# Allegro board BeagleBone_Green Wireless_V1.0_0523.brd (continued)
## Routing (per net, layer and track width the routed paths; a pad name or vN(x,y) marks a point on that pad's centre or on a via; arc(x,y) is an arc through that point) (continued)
LEDDC: length 19.3
  TOP w0.121: v1(19.7,108.05) 19.41,108.05 19.32,108.14 Q2.3 ; v1(4.57,110.08) 4.7,109.96 D5.1
  LYR3 w0.133: v1(4.57,110.08) 5.71,110.08 5.87,110.24 7.65,110.24 9.45,112.04 15.09,112.04 19.08,108.05 v1(19.7,108.05)
MMC0_CD: length 83.8
  TOP w0.121: v1(42.32,88.73) U5.C15
  LYR3 w0.127: v1(37.06,83.78) 37.33,84.05 47.9,84.05
  LYR3 w0.133: 47.9,84.05 48.79,84.94 53.11,84.94 53.8,84.25 54.61,84.25 55.91,82.96 55.91,81.13 56.62,80.42 68.38,80.42 72.67,84.71 72.67,91.31 75.57,94.21 v1(76.58,94.21) 77.93,95.55 77.93,103.9 v1(75.62,106.2)
  BOTTOM w0.121: 36.8,84.41 36.8,85.29 37.49,85.98 40.93,85.98 41.92,86.97 41.92,88.33 v1(42.32,88.73) ; P10.10 73.19,108.82 73.58,108.43 73.58,108.24 v1(75.62,106.2) ; R157.1 v1(76.58,94.21) ; 35.92,83.86 P2.19
  BOTTOM w0.127: 35.92,83.86 36.57,83.86 36.65,83.78 v1(37.06,83.78) 37.06,84.16 36.8,84.41
MMC0_CLKO: length 84
  TOP w0.121: v1(33.6,85.34) 33.6,85.9 34.8,87.1 34.8,88.3 37.66,91.16 38.48,91.16 40.06,92.74 40.72,92.74 U5.G17
  LYR3 w0.133: v1(84.53,94.41) 84.3,94.64 83.27,94.64 81.25,92.62 81.25,91.12 80.95,90.82 80.95,86.26 77.04,82.35 72.55,82.35 69.48,79.27 56.82,79.27 54.43,76.88 50.32,76.88 50.32,76.89 49.1,76.89 48.23,77.75 48.23,78.81 47.21,79.83 46.48,79.83 45.22,81.1 45.22,81.47 43.78,82.91 40.67,82.91 39.6,81.84 36.78,81.84 36.09,81.15 35.57,81.15 33.22,83.5 33.22,84.96 v1(33.6,85.34)
  BOTTOM w0.121: P10.5 85.09,94.97 v1(84.53,94.41) 85.34,93.6 R152.2
MMC0_CMD: length 94.8
  TOP w0.121: U5.G18 40.04,92.34 38.61,90.91 37.75,90.91 35.1,88.26 35.1,86.77 34.01,85.67 34.01,85.04 v1(33.63,84.66)
  LYR3 w0.133: v1(33.63,84.66) 33.63,83.96 35.54,82.04 36.2,82.04 36.32,82.17 39.6,82.17 40.57,83.14 44.11,83.14 45.62,81.64 45.62,81.03 46.48,80.16 47.45,80.16 48.64,78.97 48.64,77.67 49.19,77.12 50.41,77.12 50.42,77.12 54.28,77.12 56.74,79.57 69.45,79.57 72.69,82.81 77,82.81 80.44,86.26 80.44,90.22 79.83,90.83 79.83,92.94 79.27,93.5 v1(79.27,94.08) 79.45,94.26 79.45,100 84.71,105.26 v1(84.71,107.57)
  BOTTOM w0.121: R151.2 79.27,93.34 v1(79.27,94.08) ; P10.3 84.39,109.21 84.71,108.89 v1(84.71,107.57)
MMC0_DAT0: length 72.9
  TOP w0.121: v1(41.52,91.94) U5.G16
  LYR3 w0.133: v1(41.1,81.89) 41.53,81.89 41.68,82.04 43.98,82.04 44.3,81.73 44.3,79.12 44.6,78.82 45.74,78.82 48.14,76.42 50.12,76.42 50.12,76.41 54.67,76.41 57,78.74 69.61,78.74 72.51,81.64 77.6,81.64 82.37,86.41 82.37,89.94 82.4,89.97 82.4,90.78 83.95,92.33 v1(83.95,94.23)
  LYR4 w0.133: v1(41.52,91.94) 41.32,91.94 39.22,89.84 39.22,86.72 39.6,86.33 39.6,83.31 41.02,81.89 v1(41.1,81.89)
  BOTTOM w0.121: P10.7 83.69,94.49 v1(83.95,94.23) 84.46,93.73 R153.2
MMC0_DAT1: length 70.9
  TOP w0.121: v1(42.32,91.94) U5.G15
  LYR3 w0.127: 49,76.65 48.24,76.65
  LYR3 w0.133: v1(41.1,82.5) 43.86,82.5 44.79,81.57 44.79,80.94 46.02,79.71 46.02,78.86 48.24,76.65 ; v1(83.24,94.03) 83.24,92.08 81.28,90.12 81.28,85.93 77.24,81.89 72.43,81.89 69.53,78.99 56.92,78.99 54.58,76.65 50.22,76.65 50.22,76.65 49,76.65
  LYR4 w0.121: 39.51,86.97 39.47,87 39.47,87.22 ; 39.85,86.62 39.85,83.75 v1(41.1,82.5) ; v1(42.32,91.94) 41.92,91.54 41.35,91.54 41.13,91.32
  LYR4 w0.133: 39.85,86.62 39.51,86.97 ; 41.13,91.32 39.47,89.66 39.47,87.22
  BOTTOM w0.121: R154.2 83.52,93.37 83.52,93.75 v1(83.24,94.03) 82.99,94.27 P10.8
MMC0_DAT2: length 86.5
  TOP w0.121: v1(34.42,84.68) 34.82,85.09 34.83,85.09 34.95,85.21 34.95,86.16 35.41,86.61 35.41,88.21 37.86,90.66 38.74,90.66 39.62,91.54 U5.F18
  LYR3 w0.133: v1(83.52,105.36) 83.52,104.78 78.7,99.96 78.7,95.95 77.47,94.72 v1(77.47,94.08) 77.01,93.62 75.49,93.62 72.92,91.06 72.92,84.58 68.52,80.18 56.52,80.18 55.63,81.07 55.63,82.72 54.4,83.95 53.64,83.95 53.05,84.54 48.83,84.54 47.42,83.13 45.49,83.13 45.02,83.61 37.71,83.61 37.49,83.39 37.22,83.39 37.2,83.37 36.14,83.37 34.82,84.68 v1(34.42,84.68)
  BOTTOM w0.121: P10.1 82.99,109.23 83.44,108.79 83.44,105.81 83.52,105.74 v1(83.52,105.36) ; R150.2 v1(77.47,94.08)
MMC0_DAT3: length 87.8
  TOP w0.121: v1(35.71,82.45) 35.44,82.72 35.34,82.72 34.92,83.13 34.92,84.83 35.2,85.11 35.2,86.05 35.71,86.56 35.71,88.14 37.99,90.41 38.86,90.41 39.58,91.13 40.71,91.13 U5.F17
  LYR3 w0.133: v1(35.71,82.45) 39.55,82.45 40.47,83.38 44.84,83.38 45.32,82.9 47.75,82.9 48.91,84.06 52.89,84.06 55.37,81.57 55.37,81 56.42,79.95 68.67,79.95 73.23,84.51 73.23,90.78 75.46,93.01 77.32,93.01 v1(78.36,94.06) 78.36,95.1 79.02,95.76 79.02,99.9 84.05,104.93 v1(84.05,107.65)
  BOTTOM w0.121: v1(84.05,107.65) 84.05,108.02 84,108.07 84,109.35 83.69,109.65 P10.2 ; R155.2 v1(78.36,94.06)
MMC1_CLK: length 36.8
  TOP w0.076: U13.M6 29.32,107.79 v1(29.49,107.62)
  TOP w0.121: v1(44.68,113.43) 44.68,113.21 45.34,112.55 45.34,106.83 46.25,105.92 46.25,105.12 47.7,103.67 47.7,102.7 48.07,102.34 48.07,101.45 47.92,101.3 47.92,100.74 U5.U9
  LYR4 w0.133: v1(44.68,113.43) 44.2,112.95 40.06,112.95 37.82,110.72 31.67,110.72 30.12,109.17 30.12,108.13 29.62,107.62 v1(29.49,107.62)
  BOTTOM w0.121: P8.21 45.03,113.84 45.03,113.79 v1(44.68,113.43) 44.58,113.33 R110.2
MMC1_CMD: length 37.8
  TOP w0.076: v1(29.49,108.18) 29.38,108.29 U13.M5
  TOP w0.121: P8.20 44.98,116.79 44.98,114.68 44.53,114.22 44.45,114.22 v1(43.76,113.54) 44.93,112.37 44.93,106.88 46,105.82 46,105.02 47.42,103.6 47.42,102.61 47.82,102.21 47.82,101.64 47.52,101.34 U5.V9
  LYR4 w0.133: v1(29.49,108.18) 29.87,108.56 29.87,109.25 31.62,111 37.62,111 40.16,113.54 v1(43.76,113.54)
  BOTTOM w0.121: v1(43.76,113.54) 43.56,113.33 R109.2
MMC1_DAT0: length 48
  TOP w0.121: U13.A3 34.75,109.29 35.03,109.56 35.03,112.47 35.73,113.18 35.73,113.67 35.37,114.03 35.37,116.09 v1(35.64,116.36) ; P8.25 50.52,115.29 49.56,114.33 48.23,114.33 47.61,113.71 47.61,111.93 47.64,111.9 47.64,111.45 46.96,110.77 46.96,107.44 47.24,107.16 47.24,105.53 48.7,104.07 48.7,104.05 49.36,103.39 49.36,101.71 49.51,101.56 49.51,100.73 U5.U7
  LYR3 w0.133: P8.25 50.29,116.56 38.25,116.56 37.67,115.98 37.03,115.98 36.65,116.36 v1(35.64,116.36)
  BOTTOM w0.121: R101.2 49.02,112.88 50.67,114.53 50.8,114.53 P8.25
MMC1_DAT1: length 37.7
  TOP w0.121: v1(47.21,112.75) 46.72,112.26 46.72,107.34 46.98,107.07 46.98,107.02 46.99,107.01 46.99,105.43 48.45,103.97 48.45,103.95 49.12,103.28 U5.V7 ; U13.A4 35.01,108.79 35.56,109.33 35.56,112.25 36.44,113.13 37.62,113.13 v1(38.02,113.54)
  LYR4 w0.133: v1(47.21,112.75) 45.96,114 40.23,114 39.57,113.33 38.23,113.33 v1(38.02,113.54)
  BOTTOM w0.121: v1(47.21,112.75) R102.2 48.13,112.75 48.77,113.39 48.89,113.39 50.42,114.91 50.42,116.43 P8.24
MMC1_DAT2: length 43.8
  TOP w0.121: v1(38.18,112.2) 37.71,112.67 37.15,112.67 37.03,112.55 37.03,112.01 36.07,111.05 36.07,109.02 35.46,108.41 35.34,108.29 U13.A5 ; v1(48.72,99.14) U5.R8
  LYR3 w0.121: 48.32,100.18 48.32,99.54 v1(48.72,99.14)
  LYR3 w0.133: v1(38.18,112.2) 38.47,112.2 38.57,112.31 42.98,112.31 44.11,111.18 44.81,111.18 47.18,108.8 47.18,107.02 47.62,106.58 47.62,100.87 48.32,100.18
  LYR4 w0.133: v1(27.43,113.39) 28.8,112.01 34.67,112.01 35.59,112.93 37.45,112.93 v1(38.18,112.2)
  BOTTOM w0.121: R103.2 v1(27.43,113.39) 27.43,114.02 P8.5
MMC1_DAT3: length 39.9
  TOP w0.076: 34.29,110.85 34.29,110.54 34.24,110.49 34.24,110.05 33.99,109.8 U13.B2
  TOP w0.121: 34.29,110.85 34.29,112.4 34.32,112.42 v1(34.32,112.47) ; v1(48.72,99.94) U5.T8
  LYR3 w0.133: v1(34.32,112.47) 34.7,112.47 34.86,112.64 42.98,112.64 44.19,111.43 44.91,111.43 47.52,108.82 47.52,107.37 47.52,107.36 47.52,107.24 47.89,106.88 47.89,101.19 48.72,100.36 v1(48.72,99.94)
  LYR4 w0.133: v1(28.7,113.39) 29.59,112.5 34.24,112.5 34.26,112.47 v1(34.32,112.47)
  BOTTOM w0.121: P8.6 27.43,116.56 27.43,114.66 v1(28.7,113.39) R104.2
MMC1_DAT4: length 41.9
  TOP w0.076: 34.77,109.66 34.65,109.54 34.59,109.54 34.26,109.54 34,109.29 U13.B3
  TOP w0.121: U5.U8 48.71,100.73 48.71,102.44 48.21,102.95 48.21,103.87 46.74,105.33 46.74,106.18 46.62,106.31 46.18,106.74 46.18,107.07 46.47,107.36 46.47,112.36 46.81,112.7 46.81,112.92 46.86,112.97 46.86,113.39 48.1,114.62 48.35,114.62 P8.23 ; v1(34.67,113.39) 34.67,113.13 34.77,113.03 34.77,109.66
  LYR3 w0.133: P8.23 48.06,116.26 38.43,116.26 37.49,115.32 37.49,114.99 36.83,114.33 35.51,114.33 34.67,113.49 v1(34.67,113.39)
  BOTTOM w0.121: P8.23 46.61,112.88 R105.2
MMC1_DAT5: length 44.9
  TOP w0.076: 34.79,109.04 34.24,109.04 U13.B4
  TOP w0.121: 34.79,109.04 34.92,109.04 35.28,109.4 35.28,112.32 36.37,113.41 37.09,113.41 37.38,113.7 37.38,116.39 v1(37.38,116.4) ; P8.22 46.48,117.5 47.51,116.47 47.51,114.85 46.76,114.1 46.76,113.63 46.62,113.49 46.62,113.08 46.56,113.02 46.56,112.8 46.22,112.47 46.22,107.46 45.94,107.18 45.94,106.58 46.49,106.02 46.49,105.23 47.96,103.76 47.96,102.85 48.32,102.49 U5.V8
  LYR3 w0.133: P8.22 46.48,117.63 45.69,116.84 38.05,116.84 37.71,116.5 37.48,116.5 v1(37.38,116.4)
  BOTTOM w0.121: R106.2 47.75,114.91 47.75,116.56 P8.22
MMC1_DAT6: length 42.6
  TOP w0.076: U13.B5 34,108.29 34.25,108.53 34.87,108.53
  TOP w0.121: v1(47.92,99.14) U5.R9 ; v1(36.47,112.2) 35.81,111.54 35.81,109.19 35.79,109.17 35.79,109.14 35.18,108.53 35.05,108.53 34.87,108.53
  LYR3 w0.133: v1(47.92,99.14) 45.03,102.02 45.03,102.06 45,102.09 45,102.16 44.99,102.17 44.99,105.79 44.98,105.79 44.98,105.87 44.42,106.43 44.42,107.75 43.31,108.86 43.31,110.13 41.91,111.53 37.15,111.53 v1(36.47,112.2)
  LYR4 w0.133: v1(36.47,112.2) 35.8,112.2 35.03,111.43 26.85,111.43 v1(24.89,113.39)
  BOTTOM w0.121: P8.3 24.89,114.02 v1(24.89,113.39) R107.2
MMC1_DAT7: length 45.6
  TOP w0.076: 34.82,108.03 34.8,108.04 34.39,108.04 34.39,108.04 34.25,108.04 U13.B6
  TOP w0.121: v1(47.92,99.94) U5.T9 ; v1(37.52,112.2) 37.29,111.97 37.29,111.81 36.32,110.84 36.32,108.91 36.22,108.82 36.22,108.76 35.48,108.03 34.82,108.03
  LYR3 w0.133: v1(47.92,99.94) 47.66,99.94 45.59,102.01 45.59,103.45 45.64,103.51 45.64,103.58 46.1,104.04 46.1,105.13 44.7,106.53 44.7,109.07 41.99,111.79 37.94,111.79 v1(37.52,112.2)
  LYR4 w0.133: v1(26.16,113.39) 27.84,111.71 34.82,111.71 35.79,112.67 36.93,112.67 37.19,112.41 37.31,112.41 v1(37.52,112.2)
  BOTTOM w0.121: R108.2 v1(26.16,113.39) 24.89,114.66 24.89,116.56 P8.4
OSC0_IN: length 19.5
  TOP w0.121: U5.V10 46.72,101.66 46.69,101.69 46.69,102.52 46.81,102.64 46.81,103.26 v1(46.65,103.42)
  LYR3 w0.133: v1(45.82,108.51) 45.82,106.55 47.14,105.23 47.14,103.91 v1(46.65,103.42)
  BOTTOM w0.121: U17.5 44.19,108.17 44.53,108.51 v1(45.82,108.51) ; R234.1 38.18,103.66 38.64,103.66
  BOTTOM w0.133: v1(46.65,103.42) 46.26,103.42 46.03,103.66 45.82,103.66 45.76,103.71 44.21,103.71 44.12,103.81 42.57,103.81 42.39,103.63 40.99,103.63 40.81,103.45 40.47,103.45 40.27,103.66 38.64,103.66
OSC0_OUT: length 22.3
  TOP w0.121: U5.U11 46.31,100.73 v1(46.31,102.97)
  LYR3 w0.133: 46.23,103.13 46.23,103.09 46.31,103.01 v1(46.31,102.97) 46.31,102.97
  BOTTOM w0.121: v1(46.31,102.97) 45.88,103.4 45.71,103.4 45.66,103.46 44.11,103.46 44.01,103.56 42.67,103.56 42.5,103.38 41.12,103.38 40.83,103.09 36.76,103.09 36.09,103.76 36.09,110.72 36.5,111.12 R235.1
OSC1_IN: length 8.2
  TOP w0.121: U5.A6 51.05,86.4 51.05,85.7 50.93,85.57 50.93,84.18 51.56,83.54 v1(51.56,82.91) 51.56,82.08 51.33,81.84 Y1.1
  BOTTOM w0.121: C21.2 51.88,82.59 v1(51.56,82.91)
OSC1_OUT: length 8.6
  TOP w0.121: U5.A4 51.52,87.01 51.75,86.78 51.75,85.51 51.56,85.32 51.56,84.43 52.45,83.54 52.83,83.54 v1(53.47,82.91) 53.47,82.08 53.7,81.84 Y1.4
  BOTTOM w0.121: C22.2 53.15,82.59 v1(53.47,82.91)
OVCUR1#: length 1.8
  TOP w0.121: R224.1 29.59,94.21 28.7,95.1 U23.25
P_BYPASS: length 2.6
  TOP w0.203: v1(21.62,84.28) 21.65,84.24 22.22,84.24 22.46,84.01 U2.47
  BOTTOM w0.381: C4.2 21.59,84.25 v1(21.62,84.28)
P_INT_LDO: length 3.1
  TOP w0.121: U2.48 22.06,83.71 21.97,83.79 21.36,83.79 21.11,84.05 21.11,84.77 21.78,85.45 C3.2
P_L1: length 1
  TOP w0.203: U2.20 24.86,76.3
  vias: v1(23.75,75.03) v1(24.38,75.03)
P_L2: length 0.6
  TOP w0.203: 26.06,76.66 U2.23
  vias: v1(26.04,75.03) v1(26.67,75.03)
PGANG: length 20
  TOP w0.121: U23.23 28.66,94.1 29.18,93.57 v1(30.23,93.57) ; v1(18.9,91.74) 18.62,91.74 18.16,91.29 D6.1
  BOTTOM w0.121: v1(18.9,91.74) 18.9,91.93 19.02,92.05 R220.2 20.12,91.62 20.12,91.54 21.69,89.97 30.3,89.97 30.86,90.53 30.86,92.56 30.49,92.93 30.49,93.33 30.24,93.57 v1(30.23,93.57)
PMIC_INT: length 24.1
  TOP w0.121: U2.45 23.26,84.48 v1(22.99,84.75) 23.05,84.75 23.75,85.45 R1.2 ; v1(38.35,84.81) 38.35,85.52 38.99,86.16 38.99,87.01 U5.B18
  LYR3 w0.133: v1(38.35,84.81) 37.85,84.3 36.2,84.3 34.59,85.9 31.67,85.9 30.63,84.86 27.51,84.86 27.18,85.19 23.43,85.19 v1(22.99,84.75)
PMIC_PGOOD: length 30.1
  TOP w0.121: U2.26 27.75,78.57 27.95,78.36 27.95,78.26 v1(28.32,77.89) ; v1(32.08,75.77) 32.83,75.77 33.15,75.45 U16.2 ; v1(42.32,87.93) U5.B15
  LYR3 w0.133: v1(28.32,77.89) 30.44,75.77 31.35,75.77 31.35,75.77 31.69,75.77 31.69,75.77 v1(32.08,75.77) 34.37,75.77 36.47,77.88 38.33,77.88 39.7,79.25 42.93,79.25 43.51,79.83 v1(43.51,79.91)
  LYR4 w0.133: v1(43.51,79.91) 43.15,80.26 43.15,84.15 42.9,84.4 42.9,85.95 42.32,86.54 v1(42.32,87.93)
PMIC_POWR_EN: length 65.5
  TOP w0.121: U2.9 19.83,79.37 v1(19.71,79.25) ; v1(50.32,88.73) U5.C6
  LYR3 w0.133: v1(59.92,75.87) 58.03,73.98 55.26,73.98 54.72,74.52 49.34,74.52 49.34,74.52 47.36,74.52 46.67,75.21 43.32,75.21 43.28,75.17 43.27,75.17 42.29,74.19 40.77,74.19 40.58,74.37 36.35,74.37 36.35,74.37 35.82,74.37 35.57,74.63 32.89,74.63 32.64,74.37 23.77,74.37 21.46,76.68 21.46,77.59 19.8,79.25 v1(19.71,79.25)
  LYR4 w0.133: v1(59.92,75.87) 59.87,75.87 59.31,76.43 59.31,81.64 56.39,84.56 56.13,84.56 54.61,86.08 51.82,86.08 50.32,87.58 v1(50.32,88.73)
PROC_A15: length 14
  TOP w0.121: v1(41.12,79.73) 40.94,79.73 39.74,80.94 39.74,85.59 40.74,86.59 41.77,86.59 42.32,87.13 U5.A15
  BOTTOM w0.121: v1(41.12,79.73) 41.99,79.73 42.6,79.12 42.6,77.82 42.48,77.7 R18.1
PSELF: length 2.6
  TOP w0.121: U23.22 28.7,93.6 29.36,92.94 R226.2 R225.1
PWR_BUT: length 63.5
  TOP w0.121: U2.25 27.33,77.67 27.81,77.19 v1(28.32,77.19)
  TOP w0.305: v1(11.63,105.31) 11.36,105.58 11.36,107.05 S3.4 11.79,107.47 11.79,109.91 11.38,110.31 S3.2
  LYR3 w0.133: v1(18.96,79.71) 19.17,79.91 19.63,79.91 20.02,79.51 20.13,79.51 21.95,77.7 21.95,77.39 22.49,76.85 24.35,76.85 25.43,75.77 26.42,75.77 27.84,77.19 v1(28.32,77.19)
  LYR4 w0.127: 30.94,74.51 30.94,71.78 32.31,70.41
  LYR4 w0.133: 30.94,74.51 28.59,76.85 28.59,76.92 v1(28.32,77.19) ; v1(11.63,105.31) 11.63,102.92 9.63,100.91 9.63,94.01 12.52,91.11 12.52,89.05 13.51,88.06 16.05,88.06 16.92,87.2 16.92,85.5 18.96,83.45 v1(18.96,79.71) ; P9.9 32.31,68.1 32.31,70.41
PWR_LEDR: length 1.5
  TOP w0.305: D1.1 5.4,106.69 5.56,106.53 R12.2
SLOW_CLK: length 8
  LYR3 w0.121: v1(67.65,105.32) 69.14,106.81 69.14,110.62 69.11,110.65 69.11,110.67 69.09,110.7 v1(69.09,111.07)
  BOTTOM w0.121: U22.1 67.17,105.35 67.31,105.49 67.49,105.49 v1(67.65,105.32) ; v1(69.09,111.07) 69.09,111.05 69.42,110.72 R213.1
SPI1_CS0: length 100.6
  TOP w0.121: v1(44.72,88.73) U5.C12
  TOP w0.127: v1(50.71,109.86) 50.72,109.86 50.75,109.83 R236.1
  LYR3 w0.127: v1(48.15,73.93) 47.62,73.93 46.57,74.98 43.41,74.98 43.38,74.94 43.37,74.94 41.72,73.3 36.51,73.3 36.14,73.66 v1(32.21,73.66)
  LYR4 w0.127: 48.15,74.52 v1(48.15,73.93) 48.15,73.22 48.07,73.14 48.07,72.17 48.74,71.5 50.65,71.5 ; v1(50.71,109.86) 51.23,110.38 51.23,112.78 50.88,113.13 50.27,113.13 47.55,110.41 46.28,110.41 43.97,108.11 42.79,108.11 38.16,103.48 36.91,103.48 34.67,101.24 34.67,99.6 34.23,99.16 34.23,98.21 34.57,97.87 36.39,97.87 36.97,97.29 36.97,95.03 35.52,93.58 35.52,89.14 34.76,88.38 34.76,87.11 35.32,86.55 35.32,83.51 35.16,83.35 35.16,78.89 34.97,78.71 34.97,77.82 33.78,76.63 33.78,75.23 v1(32.21,73.66)
  LYR4 w0.133: P9.28 52.17,71.5 50.65,71.5 ; v1(44.72,88.73) 44.72,86.98 45.31,86.39 45.31,80.98 46.86,79.43 46.86,78.97 47.11,78.72 47.11,77.32 48.15,76.28 48.15,74.52
SPI1_D0: length 107.6
  TOP w0.121: U5.B13 v1(43.92,87.93)
  TOP w0.127: v1(50.67,108.15) 50.88,107.95 R238.1
  LYR3 w0.127: v1(46.3,74.52) 46.08,74.75 43.51,74.75 43.47,74.71 43.46,74.71 41.82,73.07 36.41,73.07 36.05,73.43 33.2,73.43 33.02,73.26 31.75,73.26 31.6,73.41 31.6,73.71 v1(31.62,73.73)
  LYR4 w0.127: v1(50.67,108.15) 50.32,108.51 50.32,109.09 50.65,109.43 51.13,109.43 51.46,109.75 51.46,112.87 50.95,113.39 50.2,113.39 47.45,110.64 46.18,110.64 43.88,108.34 42.69,108.34 38.07,103.71 36.82,103.71 34.44,101.33 34.44,99.7 34,99.26 34,98.12 34.48,97.64 36.29,97.64 36.74,97.2 36.74,95.12 35.29,93.68 35.29,89.23 34.53,88.48 34.53,87.01 35.09,86.46 35.09,83.6 34.84,83.35 34.84,78.9 34.74,78.8 34.74,77.92 33.55,76.72 33.55,75.66 31.89,74 31.89,74 v1(31.62,73.73) ; 47.37,73.2 46.88,73.7 46.62,73.7 46.3,74.02 v1(46.3,74.52) 46.3,75.93 46.35,75.98
  LYR4 w0.133: 47.37,73.2 47.5,73.08 47.5,71.93 48.43,71 49.28,71 50.21,70.06 50.21,69.22 51,68.43 53.21,68.43 53.47,68.17 55.5,68.17 56.64,67.03 ; 46.35,75.98 46.54,76.16 46.54,76.45 46.57,76.48 46.57,77.64 46.35,77.85 46.35,77.88 45.14,79.1 45.14,80.25 44.81,80.58 44.81,84.43 44.06,85.18 44.06,86.37 43.51,86.92 43.51,87.53 v1(43.92,87.93)
SPI1_D1: length 111.6
  TOP w0.121: v1(44.72,89.54) U5.D12
  TOP w0.127: R237.1 v1(50.72,108.92)
  LYR3 w0.127: v1(50.67,73.38) 50.04,74.02 48.81,74.02 48.5,73.71 48.5,73.7 48.33,73.52 47.23,73.52 47.03,73.72 46.12,73.72 45.55,74.29 43.7,74.29 43.66,74.25 43.65,74.25 42.01,72.61 38.24,72.61 37.64,72.01 37.31,72.01 36.85,72.47 35.58,72.47 35.15,72.9 v1(31.5,72.9)
  LYR4 w0.121: v1(44.72,89.54) 45.12,89.14 45.12,88.24 ; v1(50.67,73.38) 50.34,73.05 50.34,72.31
  LYR4 w0.127: 50.34,73.76 50.34,73.71 v1(50.67,73.38) ; 52.33,71.67 52.33,71.67 52.27,71.73 50.92,71.73 50.34,72.31 ; v1(50.72,108.92) 51.1,108.92 51.69,109.5 51.69,112.97 51.04,113.61 50.1,113.61 47.36,110.87 46.09,110.87 43.78,108.57 42.6,108.57 37.97,103.94 36.72,103.94 34.21,101.43 34.21,99.79 33.77,99.35 33.77,98.02 34.44,97.36 36.25,97.36 36.51,97.1 36.51,95.22 35.06,93.77 35.06,89.33 34.31,88.57 34.31,86.92 34.85,86.37 34.85,83.69 34.52,83.35 34.52,78.01 33.32,76.82 33.32,75.79 32.18,74.65 31.88,74.65 31.22,73.99 31.22,73.18 v1(31.5,72.9)
  LYR4 w0.133: 52.33,71.67 53.48,70.53 54.5,70.53 55.06,69.97 55.06,69.7 55.19,69.57 56.64,69.57 ; 45.12,88.24 45.12,87.01 45.55,86.58 45.55,81.23 46.59,80.19 46.85,80.19 47.69,79.35 47.69,78.47 47.35,78.13 47.35,77.42 48.44,76.33 48.44,76.25 50.34,74.35 50.34,73.76
SPI1_SCLK: length 94.1
  TOP w0.121: U5.A13 v1(43.92,87.13)
  TOP w0.127: v1(53.82,105.77) 53.8,105.77 53.54,106.02 R239.1
  LYR3 w0.127: v1(35.76,73.03) 35.95,72.84 41.91,72.84 43.56,74.48 43.57,74.48 43.6,74.52 45.72,74.52 46.12,74.12 v1(46.81,74.12)
  LYR4 w0.127: v1(53.82,105.77) 53.49,106.1 43.33,106.1 43.2,105.96 41.96,105.96 38.96,102.97 38.96,101.79 39.07,101.69 39.07,100.07 38.98,99.99 38.98,99.94 38.95,99.91 38.95,99.42 38.53,99.01 38.53,97.76 38.79,97.5 38.79,94.49 38.25,93.95 37.85,93.95 36.45,92.56 36.45,88.64 35.74,87.92 35.74,87.55 36.25,87.04 36.25,83.73 36.43,83.54 36.43,83.49 36.6,83.32 36.6,83.31 36.71,83.21 36.71,78.44 34.52,76.25 34.52,73.89 35.38,73.03 v1(35.76,73.03) ; 46.84,74.35 46.84,74.15 v1(46.81,74.12) 47.73,73.2 47.73,73.2
  LYR4 w0.133: 46.84,74.35 46.84,78.21 46,79.04 46,79.81 45.06,80.75 45.06,84.68 44.35,85.39 44.35,86.7 v1(43.92,87.13) ; 47.73,73.2 47.73,72.03 48.53,71.23 49.38,71.23 50.07,70.54 52.15,70.54 53.09,69.6 53.09,69.11 53.77,68.43 57.78,68.43 P9.31
SYS_5V: length 53.6
  TOP w0.203: U2.8 20.35,79.77 v1(20.19,79.92) 20.44,80.17 U2.7 ; v1(28.3,81.46) 28.19,81.36 28.19,81.23 27.97,81 27.37,81 U2.32 ; v1(20.19,82.52) 20.55,82.17 U2.2 ; U2.22 25.66,76.43 v1(25.53,76.3) 25.26,76.57 U2.21 ; v1(24.38,84.24) 24.46,84.13 U2.42 ; U2.39 v1(25.66,84.24)
  LYR4 w0.381: v1(20.6,101.85) 20.6,102.49 20.22,102.87 20.22,107.82 20.23,107.83 20.23,108.27 18.67,109.83 v1(16.13,109.83)
  LYR4 w0.889: 28.04,70.23 P9.8 ; P9.8 29.36,70.23 ; P9.8 28.04,68.91 ; P9.8 29.36,68.91
  LYR4 w1.016: P9.7 P9.8
  BOTTOM w0.33: U20.7 23.74,102.85 23.88,102.72
  BOTTOM w0.381: C10.2 20.38,79.73 v1(20.19,79.92) ; v1(25.66,84.24) 25.66,83.61 C13.2 24.89,83.48 24.89,83.99 24.64,84.24 v1(24.38,84.24) ; R227.2 26.64,90.78 26.49,90.93 v1(26.48,90.93) ; v1(28.3,81.46) 28.68,81.08 28.68,79.83 29.11,79.4 29.11,76.56 ; 9.65,112.12 9.65,113 ; 9.65,113 10.54,113 10.74,112.8 14.76,112.8 16.13,111.43 v1(16.13,109.83) ; 9.65,113 9.65,114.78
  BOTTOM w0.889: P9.8 28.7,70.43 ; P9.8 29.57,69.57 ; P9.8 28.7,68.71 ; P9.8 27.84,69.57 ; 28.7,67.89 P9.7 27.84,67.03
  vias: v1(24.64,101.5) v1(24.76,100.89) v1(25.25,101.19) v1(28.45,99.29) v1(28.88,99.7) v1(28.93,99.01)
SYS_RESETN: length 92.4
  TOP w0.121: v1(43.81,81.64) 43.31,81.64 43.05,81.89 43.05,83.79 44.32,85.06 45.21,85.06 46.1,85.95 46.1,86.59 46.72,87.2 U5.A10 ; v1(37.47,79.01) 37.04,78.58 37.04,77.87 37.15,77.76 37.15,77.15 36.76,76.76 36.73,76.76 35.57,75.59 35.57,74.99 35.23,74.65 R14.2 35.31,74.4 35.81,74.4 36.07,74.14 ; P9.10 32.5,70.83 U16.4 32.5,73.11 32.64,73.25 33.02,73.25 33.27,73 33.27,71.86 33.4,71.73 34.14,71.73 34.26,71.85 34.26,73.16 34.61,73.51 C24.1
  TOP w0.127: C30.1 36.55,73.52 36.16,73.91 ; 36.16,73.91 36.07,74 36.07,74.14 ; 36.16,73.91 36.1,73.91 36.09,73.91 35.46,73.91 C24.1
  TOP w0.305: v1(13.77,113.56) 13.13,114.2 S1.4 S1.2
  LYR3 w0.133: v1(37.47,79.01) 38.5,79.01 40.61,81.13 43.31,81.13 v1(43.81,81.64)
  LYR4 w0.121: v1(29.67,83.44) 29.92,83.69 29.92,85.95 29.01,86.87 29.01,91.01 29.9,91.9 29.9,93.32 29.79,93.42 29.79,101.24 27.76,103.28 24.87,103.28 21.74,106.4 21.74,108.56 19.56,110.74 17.88,110.74 15.06,113.56 v1(13.77,113.56)
  BOTTOM w0.121: v1(29.67,83.44) 31.39,83.44 32,82.83 32,82.21 32.89,81.32 P2.15 35.19,81.32 35.5,81.01 36.28,81.01 36.73,80.57 36.73,79.74 37.3,79.17 37.34,79.17 37.46,79.04 37.46,79.02 v1(37.47,79.01)
TESTOUT: length 2.9
  TOP w0.121: U5.A3 52.83,87.02 TP3.1
TIMER4: length 33.9
  TOP w0.121: v1(49.52,99.14) U5.R7
  LYR3 w0.121: 49.12,100.18 49.12,99.54 v1(49.52,99.14)
  LYR3 w0.133: 49.12,100.18 49.12,100.46 48.15,101.43 48.15,107.07 47.75,107.47 47.75,108.97 45.03,111.68 44.27,111.68 43.02,112.93 36.27,112.93 35.76,113.44 v1(35.33,113.44)
  LYR4 w0.133: P8.7 28.7,114.27 30.1,112.88 34.9,112.88 35.33,113.31 v1(35.33,113.44)
TIMER5: length 30.6
  TOP w0.121: v1(50.32,99.94) U5.T6
  LYR3 w0.133: v1(50.32,99.94) 50.32,100.53 49.47,101.38 49.47,106.67 48.39,107.75 48.39,109.17 45.29,112.27 44.4,112.27 42.58,114.09 42.5,114.09 42.39,114.2 37.31,114.2 v1(36.98,113.87)
  LYR4 w0.133: v1(36.98,113.87) 36.58,114.27 32.26,114.27 P8.9
TIMER6: length 34.9
  TOP w0.121: U5.U6 50.31,100.73 50.31,101.6 49.86,102.06 49.86,103.59 49.2,104.25 49.2,104.28 47.76,105.71 47.76,107.34 47.73,107.38 47.73,107.39 47.47,107.65 47.47,110.54 48.21,111.28 48.21,112.86 48.26,112.91 v1(48.26,113.44)
  LYR4 w0.133: P8.10 32.26,116.81 47.09,116.81 47.83,116.08 47.83,113.92 48.26,113.49 v1(48.26,113.44)
TIMER7: length 34.6
  TOP w0.121: v1(49.52,99.94) U5.T7
  LYR3 w0.133: v1(49.52,99.94) 49.52,100.94 49.15,101.31 49.15,106.58 48.08,107.65 48.08,109.04 45.14,111.99 44.32,111.99 42.46,113.86 42.4,113.86 42.29,113.96 37.71,113.96 37.21,113.46 36.63,113.46 v1(36.27,113.82)
  LYR4 w0.133: P8.8 29.97,116.56 29.97,115.09 31.17,113.89 35.81,113.89 35.89,113.82 v1(36.27,113.82)
U5_R13: length 7.2
  TOP w0.121: v1(43.92,99.14) U5.R13
  LYR3 w0.121: v1(43.92,99.14) 44.32,99.54 44.32,99.76 44.32,99.77 44.32,100.1 44.32,100.11 44.32,100.3
  LYR3 w0.133: 44.32,100.3 44.11,100.51 44.11,100.67 43.49,101.29 v1(43.49,104.6)
  BOTTOM w0.133: v1(43.49,104.6) 43.49,105.1 R160.1
U5_T13: length 10.9
  TOP w0.121: v1(43.92,99.94) U5.T13
  LYR3 w0.133: v1(43.92,99.94) 43.92,100.31 43.79,100.43 43.79,100.58 43.15,101.23 43.15,104.3 v1(42.88,104.57)
  BOTTOM w0.121: v1(42.88,104.57) 43.09,104.36 43.09,104.36 43.32,104.12 44.16,104.12 44.32,103.97 45.87,103.97 45.92,103.91 47.32,103.91 47.37,103.86 R161.1
UART0_RX: length 28.2
  TOP w0.121: v1(42.32,90.34) U5.E15
  LYR4 w0.133: v1(42.32,90.34) 41.9,89.92 41.36,89.92 40.85,89.4 40.85,86.51 41.81,85.55 41.81,83.67 42.09,83.39 42.09,80.37 42.16,80.3 42.16,80.29 42.2,80.26 42.2,80.15 42.21,80.13 42.21,79.87 42.4,79.69 42.4,79.42 44.07,77.74 44.47,77.74 44.96,77.26 v1(44.96,76.82)
  BOTTOM w0.121: U15.6 54.62,76.8 53.72,77.7 51.56,77.7 50.68,76.82 v1(44.96,76.82)
UART0_TX: length 27.5
  TOP w0.121: v1(41.52,90.34) U5.E16
  LYR4 w0.133: v1(41.52,90.34) 41.41,90.34 40.59,89.51 40.59,85.98 40.97,85.6 40.97,83.95 41.81,83.11 41.81,79.6 43.92,77.49 44.07,77.49 v1(44.34,77.22)
  BOTTOM w0.121: v1(44.34,77.22) 50.57,77.22 51.31,77.95 53.98,77.95 54.62,77.3 U15.5
UART1_RXD: length 27.5
  TOP w0.121: U5.D16 41.53,89.55 v1(41.53,89.51) ; P9.26 51.18,69.57 49.89,70.87 47.73,70.87 47.09,71.5 46.38,71.5 45.09,72.8 v1(45.09,73.79)
  LYR4 w0.121: v1(41.53,89.51) 41.92,89.12 41.92,86.96 41.96,86.92
  LYR4 w0.133: v1(45.09,73.79) 45.39,74.09 45.39,76.01 45.83,76.45 45.83,76.74 45.86,76.77 45.86,77.35 44.76,78.45 44.37,78.45 43.1,79.71 43.1,79.98 42.92,80.17 42.92,80.42 42.9,80.44 42.9,83.92 42.6,84.23 42.6,85.9 41.96,86.54 41.96,86.92
UART1_TXD: length 25
  TOP w0.121: v1(42.32,89.54) U5.D15
  LYR4 w0.121: 42.72,88.49 42.72,89.14 v1(42.32,89.54)
  LYR4 w0.133: P9.24 48.07,69.57 47.11,70.53 46.82,70.53 45.19,72.16 45.19,73.18 45.64,73.63 45.64,75.93 46.07,76.36 46.07,76.64 46.1,76.67 46.1,77.45 44.86,78.68 44.46,78.68 44.02,79.13 44.02,79.98 43.41,80.59 43.41,84.28 43.14,84.55 43.14,86.13 42.73,86.53 42.73,88.48 42.72,88.49
UART2_RXD: length 94.4
  TOP w0.121: J5.1 79.44,101.53 79.97,100.99 81.36,100.99 v1(82.3,100.05) ; P9.22 44.96,71.09 43.09,71.09 42.2,71.98 42.2,75.17 v1(41.94,75.44) 41.5,75.87 40.77,75.87 39.49,77.15 39.49,85.69 41.12,87.32 U5.A17
  LYR3 w0.133: v1(82.3,100.05) 82.68,100.05 85.47,97.26 85.47,91.92 84.58,91.03 v1(84.58,90.65) 84.73,90.5 84.73,85.55 83.29,84.1 83.29,81.86 80.06,78.64 77.2,78.64 77.19,78.63 70.83,78.63 69.8,77.6 57.19,77.6 55.06,75.47 49.73,75.47 49.73,75.48 47.75,75.48 47.06,76.16 42.92,76.16 42.88,76.12 42.62,76.12 v1(41.94,75.44)
  BOTTOM w0.121: C204.1 84.96,90.27 v1(84.58,90.65)
UART2_TXD: length 96.4
  TOP w0.121: v1(82.17,99.16) 81.8,99.53 J5.2 ; U5.B17 40.72,87.94 40.72,87.3 39.24,85.83 39.24,77.04 40.87,75.41 v1(41.27,75.41) 41.91,74.78 41.91,71.92 43.12,70.71 44.14,70.71 45.21,69.64 45.21,68.3 P9.21
  LYR3 w0.133: v1(41.27,75.41) 42.24,76.38 42.81,76.38 42.83,76.4 47.16,76.4 47.85,75.71 49.83,75.71 49.83,75.71 54.97,75.71 57.09,77.83 69.7,77.83 70.76,78.89 79.93,78.89 82.98,81.94 82.98,84.25 84.32,85.59 84.32,90.28 v1(83.95,90.65) 83.95,90.78 85.22,92.05 85.22,97.13 83.44,98.91 82.42,98.91 v1(82.17,99.16)
  BOTTOM w0.121: v1(83.95,90.65) C205.1
UART3_CTSN: length 32.1
  TOP w0.121: U5.M17 40.72,95.94 39.67,95.94 39.4,96.22 37.85,96.22 35.79,98.27 v1(35.61,98.27) ; v1(50.65,112.7) 51.21,112.7 R210.1 R200.1
  LYR4 w0.121: 45.45,107.88 45.76,107.88 46.22,108.34 46.22,108.65 50.27,112.7 v1(50.65,112.7)
  LYR4 w0.133: 45.45,107.88 42.88,107.88 38.26,103.25 37.09,103.25 37.09,103.25 37.01,103.25 34.9,101.14 34.9,99.3 35.04,99.16 35.04,98.93 35.34,98.63 35.34,98.54 v1(35.61,98.27)
UART3_RTSN: length 37.4
  TOP w0.121: R209.1 50.11,110 50.42,110.31 v1(50.42,110.52) 50.85,110.52 51.17,110.85 R199.1 ; U5.M18 39.88,96.34 39.67,96.55 38,96.55 v1(35.69,98.86)
  BOTTOM w0.121: v1(35.69,98.86) 35.23,99.31 35.23,111.94 35.9,112.6 40.62,112.6 42.49,110.73 48.14,110.73 48.79,110.08 50.27,110.08 50.42,110.23 v1(50.42,110.52)
UART3_RXD: length 43
  TOP w0.121: U21.14 53.2,110.71 53.1,110.81 v1(53.09,110.81) ; U5.L17 40.88,95.54 40.48,95.14 38.14,95.14 35.73,97.55 35.72,97.55 35.13,98.14 35.13,98.5 v1(34.63,99)
  BOTTOM w0.121: v1(53.09,110.81) 52.46,110.81 52.25,110.59 51.26,110.59 50.69,111.17 50.15,111.17 49.62,110.64 49,110.64 48.41,111.23 42.69,111.23 40.79,113.13 35.61,113.13 34.63,112.15 v1(34.63,99)
UART3_TXD: length 44.4
  TOP w0.121: v1(34.73,98.28) 34.73,98.19 35.62,97.3 35.62,97.3 38.03,94.89 38.18,94.89 38.23,94.84 39.6,94.84 40.1,94.34 40.48,94.34 40.72,94.58 40.72,94.9 40.95,95.13 41.51,95.13 U5.L16 ; U21.15 53.29,110.21 53.26,110.24 v1(53.09,110.24)
  BOTTOM w0.121: v1(34.73,98.28) 35.03,98.58 35.03,99.16 34.95,99.24 34.95,112.06 35.74,112.85 40.72,112.85 42.59,110.98 48.3,110.98 48.95,110.33 49.66,110.33 50.25,110.92 50.58,110.92 51.27,110.24 v1(53.09,110.24)
UART4_RXD: length 42.1
  TOP w0.121: U5.T17 40.72,99.94 40.1,99.94 38.91,101.12 38.91,101.17 38.61,101.47 38.61,101.7 v1(38.48,101.83)
  LYR4 w0.133: P9.11 34.49,67.74 34.49,68.93 34.74,69.17 34.74,69.97 34.29,70.41 34.29,76.48 36.47,78.66 36.47,83.06 36.37,83.16 36.37,83.17 36.2,83.34 36.2,83.45 36.02,83.63 36.02,86.94 35.48,87.48 35.48,88.06 36.22,88.8 36.22,93.27 37.67,94.72 37.67,99.29 38.05,99.67 38.38,99.67 38.41,99.7 38.42,99.7 38.66,99.93 38.66,99.95 38.75,100.04 38.75,101.56 v1(38.48,101.83)
UART4_TXD: length 39.8
  TOP w0.121: U5.U17 40.71,100.74 40.08,100.74 39.86,100.96 39.86,101.09 v1(39.6,101.35)
  LYR4 w0.127: 36.84,83.41 36.66,83.58 36.66,83.64 36.59,83.71 36.59,87.57 36.73,87.71 36.73,88.95
  LYR4 w0.133: v1(39.6,101.35) 39.6,100.28 39.22,99.9 39.22,99.85 39.18,99.81 39.18,99.32 38.77,98.91 38.77,97.86 39.02,97.6 39.02,94.14 37.44,92.56 37.44,91.59 36.73,90.88 36.73,88.95 ; 36.84,83.41 37.01,83.24 37.01,78.41 36.47,77.88 36.47,77.84 35.84,77.21 35.84,76.6 36.49,75.95 36.49,73.12 35.1,71.72 35.1,69.11 35.53,68.67 35.53,67.82 P9.13
USB0_DM: length 42.4
  TOP w0.114: U5.N18 40.32,96.98 40.16,96.82 39.88,96.82 39.75,96.95 39.75,97.38 39.62,97.51 38.03,97.51 36.42,99.11 36.25,99.11 36.05,99.31 36.05,99.48 35.97,99.57 v1(35.86,99.57)
  LYR3 w0.127: v1(35.86,99.57) 36.04,99.75 36.04,100 35.56,100.48 29.92,100.48 29.62,100.18 27.46,100.18 22.88,104.75 22.88,104.89 22.65,105.13 17.23,105.13 13.54,108.81 13.54,109.65 13.27,109.92 12.65,109.92 v1(12.4,109.67)
  BOTTOM w0.114: P4.2 7.04,110.13 7.22,110.32 8.26,110.32 8.57,110.01 9.09,110.01 9.65,109.45 10.13,109.93 12.13,109.93 v1(12.4,109.67)
USB0_DP: length 42.4
  TOP w0.114: v1(36.45,99.59) 36.45,99.48 38.15,97.78 39.91,97.78 40.16,97.53 40.72,97.53 U5.N17
  LYR3 w0.127: v1(36.45,99.59) 36.35,99.7 36.35,100.13 35.69,100.79 29.79,100.79 29.49,100.48 27.58,100.48 23.19,104.88 23.19,105.02 22.77,105.43 17.35,105.43 13.84,108.94 13.84,109.78 13.4,110.22 12.65,110.22 v1(12.4,110.47)
  BOTTOM w0.114: P4.3 7.04,110.78 7.22,110.6 8.38,110.6 8.69,110.29 9.22,110.29 9.65,110.72 10.16,110.21 12.13,110.21 v1(12.4,110.47)
USB0_ID: length 46.2
  TOP w0.121: U5.P16 v1(41.52,98.34)
  LYR3 w0.133: v1(41.52,98.34) 41.89,98.71 41.89,100.15 40.82,101.22 40.82,101.63 39.22,103.23 35.79,103.23 35.56,103.46 25.37,103.46 23.97,104.86 23.96,104.86 23.73,105.1 23.73,105.1 22.99,105.84 17.7,105.84 17.16,106.38 17.15,106.38 16.92,106.62 16.92,106.63 v1(16.56,106.98)
  BOTTOM w0.121: v1(16.56,106.98) 16.56,107.78 15.72,108.62 15.72,111.23 14.71,112.24 13.21,112.24 D23.2 11.61,111.61 11.23,111.99 10.54,111.99 10.16,111.61 8.24,111.61 8.06,111.43 P4.4
USB1_DM: length 19.6
  TOP w0.114: U23.1 27.15,98.3 27.1,98.35 27.1,98.96 28.22,100.08 28.22,100.63 v1(28.61,101.02) ; v1(37.62,100.1) 37.54,100.02 37.54,99.86 37.73,99.67 38.57,99.67 39.38,98.86 40.2,98.86 U5.R18
  LYR3 w0.127: v1(37.62,100.1) 37.49,99.97 37.19,99.97 37.08,100.08 37.08,100.28 37.36,100.56 37.36,100.91 36.53,101.75 28.57,101.75 28.57,101.75 28.27,101.75 28.13,101.61 28.13,101.28 28.3,101.12 28.51,101.12 v1(28.61,101.02)
USB1_DP: length 19.7
  TOP w0.114: U23.2 26.65,98.3 26.76,98.41 26.76,98.52 26.82,98.58 26.82,99.07 27.94,100.19 27.94,100.74 27.8,100.88 v1(27.8,101.02) ; U5.R17 41.04,98.74 40.64,99.14 39.5,99.14 38.53,100.1 v1(38.25,100.1)
  LYR3 w0.127: v1(38.25,100.1) 38.13,100.23 38.07,100.23 37.92,100.38 37.67,100.63 37.67,101.04 36.65,102.06 28.7,102.06 28.14,102.06 27.8,101.72 v1(27.8,101.02)
USB1_DRVVBUS: length 59.3
  TOP w0.121: U5.F15 v1(42.32,91.14)
  LYR3 w0.127: 40.67,73.95 40.86,73.76 v1(41.25,73.76)
  LYR3 w0.133: v1(8.38,74.27) 8.77,74.27 8.78,74.26 11.46,74.26 11.52,74.27 11.57,74.29 11.61,74.32 12.1,74.32 12.11,74.31 12.16,74.28 12.22,74.27 12.26,74.26 13.37,74.26 13.39,74.28 14.05,74.28 14.1,74.29 14.16,74.31 14.17,74.32 14.78,74.32 14.83,74.3 14.88,74.28 14.92,74.28 15.93,74.28 15.97,74.32 23.49,74.32 23.68,74.14 32.74,74.14 32.92,74.32 35.54,74.32 35.72,74.14 36.45,74.14 36.45,74.14 40.49,74.14 40.67,73.95
  LYR4 w0.121: 40.33,89.77 41.69,91.14 v1(42.32,91.14)
  LYR4 w0.127: v1(41.25,73.76) 41.83,73.76
  LYR4 w0.133: 41.83,73.76 43.97,75.9 43.97,77.06 41.53,79.5 41.53,82.85 40.11,84.28 40.11,86.22 40.33,86.44 40.33,89.77
  BOTTOM w0.121: v1(8.38,74.27) 8.25,74.4 8.25,75.92 8.13,76.05 R221.2 7.24,76.17 6.87,76.54 U24.4
USB1_ID: length 2.6
  TOP w0.121: v1(40.72,98.34) 40.77,98.29 U5.P17
  BOTTOM w0.121: R49.2 40.26,99.87 40.72,99.42 v1(40.72,98.34)
USB1_OCN: length 50.9
  TOP w0.121: R224.2 30.73,93.83 v1(30.99,93.57) ; v1(41.48,99.98) 41.5,99.96 41.5,99.95 U5.T16
  LYR3 w0.133: v1(30.99,93.57) 30.99,95.86 32.69,97.56 35.79,97.56 37.85,99.62 38.68,99.62 39.05,99.98 v1(41.48,99.98)
  BOTTOM w0.121: v1(30.99,93.57) 30.99,92.81 31.11,92.68 31.11,90.42 30.3,89.61 22.58,89.61 16.05,83.08 16.05,80.16 14.78,78.89 11.1,78.89 10.87,78.66 8.79,78.66 8.38,78.26 R223.1 7.47,78.99 7.09,78.99 6.87,78.78 U24.3
USB1_VBUS: length 25.3
  TOP w0.305: v1(37.71,102.4) 37.71,102.33 37.71,102.32 37.71,101.89 38.57,101.03 38.57,100.98 39.96,99.6 40,99.6 40.06,99.54 U5.T18
  LYR3 w0.381: v1(37.71,102.4) 37.59,102.52 37.59,102.53 37.28,102.84 37.27,102.84 37.24,102.87 35.56,102.87 35.33,103.1 27.94,103.1 v1(27,102.16)
  LYR4 w0.381: v1(21.06,101.22) 21.06,101.04 21.44,100.66 22.76,100.66 24.26,102.16 v1(27,102.16)
  BOTTOM w0.381: FB8.1 18.58,100.54 19.25,101.22 v1(21.06,101.22)
USB_DC: length 35.5
  LYR3 w0.381: v1(16.05,107.57) 17.63,107.57 17.93,107.26 18.4,107.26 18.45,107.21 23.73,107.21 27.03,103.91 35.79,103.91 36.07,103.63 39.42,103.63 40.08,102.97 v1(41.27,102.97)
  BOTTOM w0.381: v1(41.27,102.97) 41.3,102.97 41.61,102.67 R159.1 ; v1(16.05,107.57) 15.32,106.83 10.03,106.83 9.65,107.21 9.65,107.42
  vias: v1(20.7,76.53) v1(20.65,75.95) v1(21.21,76.17) v2(3.94,75.34) v2(3.91,74.4) v2(3.96,76.38) v2(6.27,75.21) v2(6.35,74.32) v2(7.85,108.97) v2(7.95,108.08) v2(8.76,108.03)
USR0: length 26.4
  TOP w0.121: Q1.2 21.34,108.05 21.72,107.67 22.86,107.67 R76.1 24.03,107.16 26.04,105.16 26.04,105 27.83,103.21 34.8,103.21 34.84,103.25 34.85,103.25 35.95,104.35 40.81,104.35 41.93,103.23 41.93,102.32 42.72,101.53 U5.V15
USR1: length 31.1
  TOP w0.121: U5.U15 43.11,100.73 43.11,101.51 42.19,102.44 42.19,103.32 40.91,104.6 40.7,104.6 35.84,104.6 35.51,104.27 35.51,104.27 34.7,103.45 27.94,103.45 26.31,105.08 26.31,105.28 24.13,107.47 24.13,109.83 R77.1 22.86,111.1 21.59,111.1 21.34,110.85 Q1.5
USR2: length 32.9
  TOP w0.121: U5.T15 42.31,99.94 v1(42.3,99.94) ; Q2.2 v1(18.67,107.74) 19.88,106.53 R78.1
  LYR3 w0.133: v1(18.67,107.74) 18.96,107.74 19.06,107.65 26.89,107.65 27.03,107.78 27.03,107.81 27.26,108.05 27.6,108.05 27.84,107.81 27.84,107.78 27.97,107.65 28.95,107.65 29.08,107.51 29.08,107.45 29.32,107.21 29.61,107.21 29.64,107.19 30.12,107.19 32.99,104.32 39.37,104.32 40.26,103.43 41.43,103.43 41.81,103.05 41.81,100.6 42.3,100.1 v1(42.3,99.94)
USR3: length 29.6
  TOP w0.121: U5.V16 41.92,101.93 41.68,102.16 41.68,103.12 41.38,103.43 40.31,103.43 39.7,104.04 36.07,104.04 34.99,102.96 27.7,102.96 25.55,105.11 25.55,105.16 24.19,106.53 R79.1 21.97,106.78 21.08,107.67 20.47,107.67 20.19,107.95 20.19,108.59 19.55,109.22 19.33,109.22 19.3,109.25 19.07,109.25 18.94,109.38 18.91,109.38 18.67,109.62 Q2.5
VDCDC1:
  vias: v1(21.46,75.03) v1(22.1,75.03)
VIO: length 20.9
  TOP w0.121: U2.18 24.06,76.8 23.56,76.3 v1(23.49,76.3) ; 32.12,74.1 31.52,74.7 v1(31.52,75.37) ; U16.5 33.8,72.86 33.4,73.26
  TOP w0.127: 33.4,73.26 33.4,73.71 33.05,74.06 32.16,74.06 32.12,74.1
  LYR3 w0.133: v1(31.52,75.37) 31.14,75.37 31.01,75.49 25.2,75.49 24.38,76.3 v1(23.49,76.3)
  BOTTOM w0.121: R7.2 19.56,79.73 19.28,79.45 19.28,79.1 19.66,78.71 21.97,78.71 23.49,77.19 v1(23.49,76.3)
VLDO1: length 6.7
  TOP w0.203: 20.45,81.77 U2.3
  TOP w0.254: v1(19.68,81.89) 19.81,81.77 20.45,81.77
  BOTTOM w0.381: R8.1 20.19,85.04 20.57,84.66 20.57,83.54 20.19,83.16 R5.1 19.94,83.02 19.72,82.8 19.72,82.78 19.57,82.63 19.57,82 v1(19.68,81.89) 19.68,81.25 R7.1
VREFP_ADC: length 7.7
  TOP w0.121: 46.99,86.84 47.12,86.97 47.12,87.94
  TOP w0.254: 47.12,87.94 U5.B9
  TOP w0.305: 46.69,86.54 46.99,86.84
  TOP w0.381: C32.1 C31.1 C33.1 45.5,83.45 R27.2 45.5,84.66 46.61,85.77 46.61,86.46 46.69,86.54
VRTC: length 37.6
  TOP w0.254: v1(49.52,89.54) U5.D7
  LYR3 w0.381: v1(48.7,86.08) 48.7,86.02 47.48,84.79 39.77,84.79 38.99,85.57 38.84,85.57 38.83,85.58 36.57,85.58 35.2,86.94 28.8,86.94 27.71,85.85 22.38,85.85 22.06,85.54 19.73,85.54 v1(19.08,84.89)
  BOTTOM w0.178: v1(50.61,86.08) 50.8,86.08 51.09,85.79 51.09,84.43 51.21,84.3 R26.1
  BOTTOM w0.381: C105.1 v1(48.7,86.08) ; R5.2 C16.1 18.92,84.73 v1(19.08,84.89)
WAKEUP: length 63.9
  TOP w0.121: U5.C5 v1(51.12,88.73) ; U2.13 22.06,76.64 22.44,76.25 v1(22.73,76.25)
  LYR3 w0.133: v1(22.73,76.25) 23.19,75.79 24.26,75.79 25.43,74.63 32.28,74.63 32.56,74.9 35.62,74.9 35.92,74.61 36.25,74.61 36.3,74.65 36.45,74.65 36.49,74.61 40.68,74.61 40.87,74.42 42.19,74.42 43.17,75.41 43.18,75.41 43.22,75.44 46.77,75.44 47.45,74.76 49.43,74.76 49.44,74.76 54.82,74.76 55.36,74.22 57.68,74.22 v1(59.94,76.48)
  LYR4 w0.133: v1(59.94,76.48) 59.82,76.61 59.82,81.64 56.39,85.06 56.13,85.06 54.86,86.33 52.01,86.33 50.67,87.67 50.67,88.29 v1(51.12,88.73)
  BOTTOM w0.121: v1(51.12,88.73) 51.52,88.33 51.52,87.67 51.56,87.62 R26.2
WL_EN: length 11.4
  TOP w0.121: U18.40 68.14,112.13 v1(68.73,111.53)
  BOTTOM w0.121: 65.57,107.15 Q4.1 65.37,107.15 64.58,107.94 64.58,108.61 64.47,108.72 R187.1 64.47,109.72 64.02,110.16 64.02,111.6 64.41,111.99 68.28,111.99 v1(68.73,111.53)
WL_IRQ: length 8.6
  TOP w0.121: R176.1 72.85,98.35 v1(72.97,98.35)
  LYR3 w0.133: v1(70.51,101.73) 72.97,99.26 v1(72.97,98.35)
  BOTTOM w0.121: v1(70.51,101.73) 70.51,101.9 69.93,102.49 69.85,102.49 69.29,103.05 69.29,103.3 68.63,103.97 U22.3
WL_SDIO_CLK: length 12.3
  TOP w0.121: R195.2 70.23,92.56 69.55,93.24 69.55,96.14 v1(68.58,97.1) 68.58,97.21 67.95,97.84 R182.1
  BOTTOM w0.121: U22.8 68.79,101.47 68.98,101.28 68.98,97.5 v1(68.58,97.1)
WL_SDIO_CMD: length 12.9
  TOP w0.121: R196.2 71.06,91.67 70.67,92.06 70.23,92.06 69.19,93.09 69.19,95.78 68.25,96.72 68.25,96.77 v1(68,97.03) 67.74,97.29 67.66,97.29 R181.1
  BOTTOM w0.121: v1(68,97.03) 68,97.46 68.73,98.2 68.73,100.77 68.54,100.97 U22.9
WL_SDIO_D0: length 10.7
  TOP w0.121: R180.1 68.83,97.61 v1(69.29,97.16) 69.29,96.77 69.8,96.27 69.8,94.97 70.94,93.83 R194.2
  BOTTOM w0.121: v1(69.29,97.16) 69.29,97.56 69.24,97.61 69.24,101.5 68.77,101.97 U22.7
WL_SDIO_D1: length 10.1
  TOP w0.121: R179.1 69.72,97.41 v1(69.95,97.18) 70.22,96.91 70.22,96.06 71.12,95.16 R193.2
  BOTTOM w0.121: v1(69.95,97.18) 69.95,97.64 69.53,98.06 69.53,101.69 68.75,102.47 U22.6
WL_SDIO_D2: length 9.5
  TOP w0.121: 72.01,96.75 71.17,96.75 v1(70.87,97.05) 70.87,97.64 R178.1
  BOTTOM w0.121: U22.5 68.66,102.97 69.82,101.8 69.82,98.47 70.87,97.43 v1(70.87,97.05)
WL_SDIO_D3: length 10.3
  TOP w0.121: v1(71.42,97.23) 71.5,97.31 ; 71.5,97.31 71.58,97.38 71.91,97.38 71.96,97.33 72.38,97.33 72.9,96.81 72.9,96.75 ; 71.5,97.31 R177.1
  BOTTOM w0.121: U22.4 68.77,103.47 69.04,103.2 69.04,102.95 70,101.98 70,101.98 70.07,101.91 70.07,99.32 71.42,97.97 v1(71.42,97.23)
WP: length 9.2
  BOTTOM w0.121: TP4.1 23.24,88.11 25.25,88.11 25.82,87.54 R156.2 26.82,87.54 26.95,87.67 26.95,88.39 27.2,88.64 28.83,88.64 29.48,87.99 U7.5
XDMA_EVENT_INTR0: length 10.7
  BOTTOM w0.121: P2.17 34.84,82.59 35.46,81.97 36.25,81.97 37.06,81.15 37.06,79.76 37.4,79.41 40.78,79.41 40.97,79.22 41.78,79.22 42.04,78.97 R18.2
XTAL1: length 6.4
  TOP w0.121: Y5.1 17.59,96.18 18.29,95.48 19.63,95.48 19.76,95.61 20.83,95.61 C183.1 21.85,95.6 U23.10
XTAL2: length 4.8
  TOP w0.121: Y5.3 19.14,94.63 19.86,95.35 20.95,95.35 21.34,94.97 C184.1 21.59,95.1 U23.11
ZQ: length 2.5
  TOP w0.121: v1(67.7,87.49) U12.L8
  BOTTOM w0.121: R99.1 68.99,87.08 68.98,87.09 68.1,87.09 v1(67.7,87.49)
N21769115: length 5.3
  TOP w0.121: R75.2 68.15,79.78 S2.1 S2.3
N22155575: length 4
  TOP w0.121: v1(42.32,98.34) U5.P15
  LYR3 w0.133: v1(42.32,98.34) 42.71,98.73 42.71,100.27 42.32,100.66 v1(42.32,100.71)
  BOTTOM w0.381: v1(42.32,100.71) 41.95,100.73 41.87,100.81 R159.2
N22248684: length 1.5
  TOP w0.121: 31.24,96.9 31.24,97.28 31.89,97.93 Y4.3
N22287501: length 3.8
  BOTTOM w0.121: U3.4 29.38,102.83 29.85,103.3 29.85,104.62 28.83,105.64 R162.1
N22287555: length 18.5
  TOP w0.121: v1(43.12,99.14) U5.R14
  LYR3 w0.121: v1(43.12,99.14) 43.52,99.54 43.52,100.48
  LYR3 w0.133: v1(32.87,105.28) 33.55,104.6 40.64,104.6 42.06,103.17 42.06,102.07 42.07,102.06 42.07,101.92 43.52,100.48
  BOTTOM w0.121: U3.2 31.88,103.48 32.13,103.73 32.13,105.13 32.28,105.28 v1(32.87,105.28)
N22420400: length 4.7
  TOP w0.203: U2.5 20.48,80.97 20.19,81.25 20.3,81.37 U2.4
  TOP w0.381: 20.19,81.25 18.67,81.25 TP5.1
N22420444: length 3.5
  TOP w0.203: 20.06,80.57 U2.6
  TOP w0.381: TP6.1 18.49,80.57 20.06,80.57
N22420447: length 4.1
  TOP w0.203: TP7.1 18.67,75.95 19.99,77.27 19.99,77.88 20.68,78.57 U2.11
N22488252: length 17.9
  TOP w0.121: U5.E17 40.72,90.34 39.56,90.34 38.75,89.53 37.92,89.53 v1(36.14,87.76)
  LYR3 w0.133: TP9.1 25.2,87.53 35.92,87.53 v1(36.14,87.76)
N22648410: length 7.5
  BOTTOM w0.121: R234.2 37.59,104.09 Y2.2 37.71,105.51 C25.1 R17.1 39.89,106.67 U17.1
N22648422: length 8
  BOTTOM w0.121: U17.2 40.13,107.17 R17.2 C26.1 38.22,108.56 Y2.1 38.3,109.9 R235.2
N22649826: length 1.4
  BOTTOM w0.121: R171.2 40.77,107.67 U17.3
N22650321: length 2.1
  BOTTOM w0.121: U17.6 44.7,107.67 R174.1 R172.2
N22650344: length 2.8
  BOTTOM w0.121: U17.7 44.19,107.17 44.32,107.04 44.32,106.53 R175.2 R173.1
N22699644: length 3.4
  TOP w0.121: R233.2 R176.2 72.39,98.97 71.56,99.8 71.37,99.8 70.94,100.23 U18.14
N22699649: length 2.1
  TOP w0.121: U18.13 70.24,100.17 70.71,99.7 70.77,99.7 71.5,98.97 R177.2
N22699658: length 2
  TOP w0.121: U18.12 69.54,99.98 70.16,99.36 70.23,99.36 70.61,98.97 R178.2
N22699663: length 1.9
  TOP w0.121: U18.11 68.84,99.79 69.27,99.36 69.34,99.36 69.72,98.97 R179.2
N22699668: length 1.8
  TOP w0.121: U18.10 68.14,99.67 68.83,98.97 R180.2
N22699673: length 2.8
  TOP w0.121: U18.6 65.34,99.99 65.53,99.8 66.42,99.8 67.06,99.16 R181.2
N22699720: length 2.4
  TOP w0.121: U18.8 66.74,99.99 66.93,99.8 67.56,99.8 67.95,99.41 R182.2
N22699759: length 2
  TOP w0.121: R183.2 59.88,112.24 60.82,111.3 U18.50
N22699762: length 1.9
  TOP w0.121: R184.2 60.2,111.35 60.95,110.6 U18.51
N22699765: length 1.9
  TOP w0.121: R185.2 60.07,110.59 60.76,109.9 U18.52
N22699768: length 1.9
  TOP w0.121: R186.2 60.32,109.83 60.58,109.58 60.81,109.58 61.18,109.2 U18.53
N22705626: length 3.1
  TOP w0.121: v1(70.87,111.48) 70.94,111.55 U18.36
  BOTTOM w0.121: v1(70.87,111.48) 70.87,110.97 70.61,110.72 70.61,109.62 OSC1.3
N22705631: length 5.4
  BOTTOM w0.381: L4.1 70.99,104.5 70.12,105.37 70.12,105.62 C167.1 70.1,106.17 70.78,106.84 OSC1.4 OSC1.1
N22709787: length 1.6
  TOP w0.121: U18.43 v1(66.04,113.13)
  BOTTOM w0.121: TP22.1 65.73,112.83 v1(66.04,113.13)
N22709790: length 1.7
  TOP w0.121: v1(66.73,113.26) 66.74,113.25 U18.42
  BOTTOM w0.121: v1(66.73,113.26) 66.73,113.19 66.92,113 66.92,112.94 TP23.1
N22711010: length 8.6
  TOP w0.381: L21.2 C200.1 75.57,111.3 ; U18.32 75.57,111.3 ; 75.57,111.3 75.57,109.42 arc(75.93,108.54) 76.81,108.18 C171.1
N22711020: length 2.4
  TOP w0.381: C171.2 80.39,108.18 80.52,108.05 J6.1
N22712983: length 22.4
  TOP w0.121: C172.1 74.68,80.31 arc(74.67,80.4) 74.64,80.48 arc(74.57,80.59) 74.55,80.71 L9.2 arc(74.74,81.28) 74.8,81.61 74.8,100.02 arc(74.67,100.68) 74.3,101.24 arc(73.9,101.43) U18.18
N22712987: length 4.1
  TOP w0.121: C172.2 74.68,77.95 L10.2 74.55,76.44 arc(74.7,75.68) J7.1
N22724780: length 31.6
  TOP w0.121: v1(58.8,113.82) R198.2 58.42,113.26 58.04,112.88 56.64,112.88 56.5,112.74 U21.10
  LYR3 w0.121: v1(67.46,111.42) 67.46,111.04 66.05,109.63
  LYR3 w0.133: 66.05,109.63 64.64,109.63 63.53,108.51 63.53,102.4 66.45,99.48 v1(66.45,99.19)
  LYR4 w0.121: v1(58.8,113.82) 60.1,112.52 66.36,112.52 v1(67.46,111.42)
  BOTTOM w0.121: v1(66.45,99.19) 66.78,98.86 67.16,98.86 67.31,99.01 67.31,99.03 67.17,99.17 U22.10
N22729983: length 4.8
  BOTTOM w0.121: U22.17 64.15,103.47 63.3,104.31 61.73,104.31 61.44,104.6 61.44,104.9 60.96,105.38 R203.2
N22729986: length 4.4
  BOTTOM w0.121: U22.16 64.22,102.97 63.12,104.07 61.49,104.07 61.06,104.5 R204.2
N22729989: length 1.5
  BOTTOM w0.121: U22.15 63.88,102.47 R205.2
N22729992: length 1.3
  BOTTOM w0.121: U22.14 63.49,101.97 R206.2
N22729995: length 1.4
  BOTTOM w0.121: U22.13 63.65,101.47 R207.2
N22729998: length 1.5
  BOTTOM w0.121: R208.2 64.04,100.97 U22.12
N22732227: length 4
  TOP w0.121: U18.27 74.09,107.8 74.55,107.34 75.21,107.34 76.18,106.37 76.18,106.29 TP14.1
N22732237: length 1.6
  TOP w0.121: TP15.1 74.49,106.73 74.12,107.1 U18.26
N22732240: length 2.1
  TOP w0.121: TP16.1 74.96,105.49 74.04,106.4 U18.25
N22732294: length 4.2
  TOP w0.121: TP17.1 60.05,100.61 59.87,100.43 59.87,100.08 60.12,99.82 62.28,99.82 62.54,100.08 U18.2
N22732297: length 5.4
  TOP w0.121: TP18.1 59.05,101.96 59.18,102.08 60.05,102.08 60.55,101.57 60.55,101.37 60.9,101.02 62.83,101.02 62.84,101.02 63.09,101.02 63.24,100.87 U18.3
N22732316: length 5.6
  TOP w0.121: U18.4 63.94,100.23 63.5,99.8 62.61,99.8 62.38,99.57 60.02,99.57 59.39,100.2 TP19.1
N22732319: length 1.8
  TOP w0.121: U18.5 64.64,100.06 65.51,99.19 TP20.1
N22733307: length 2.9
  BOTTOM w0.305: U19.4 75.93,85.79 76.45,86.31 R215.1 R214.2
N22766342: length 1.9
  TOP w0.254: U23.8 22.5,96.6 21.97,97.13 R218.1
N22767849: length 2.2
  TOP w0.121: U23.26 30.31,95.6 TP24.1
N22767859: length 4.4
  TOP w0.121: U23.18 25.65,91.03 25.4,90.78 24.79,90.78 23.9,89.89 TP25.1
N22768480: length 1.8
  TOP w0.381: v1(19.08,92.48) 18.43,92.48 D6.2
  BOTTOM w0.381: R219.2 19.53,92.94 v1(19.08,92.48)
N22769591: length 4.3
  BOTTOM w0.629: 13.71,100.05 J8.A1 ; J8.A1 15.24,101.57 ; J8.A1 13.71,101.57 ; J8.A1 15.24,100.05
N22769632: length 1.7
  BOTTOM w0.629: 11.26,100.22 J8.B1 12.44,100.22
N22770199: length 3.1
  BOTTOM w0.629: J9.A1 15.24,82.37 ; J9.A1 13.71,82.37 ; J9.A1 14.47,83.13 ; J9.A1 14.47,81.6
N22770224: length 2.3
  BOTTOM w0.629: J9.B1 11.85,83.13 ; J9.B1 11.09,82.37 ; J9.B1 11.85,81.6
N22776606: length 2.8
  BOTTOM w0.254: R222.2 8.19,79.41 6.67,79.41 6.22,78.97 U24.2
N22780216: length 1.4
  TOP w0.381: D7.2 72.2,88.56 R229.2
N22783783: length 1.6
  TOP w0.381: D8.2 72.01,86.27 72.01,87.22 R230.2
N22784813: length 6.8
  TOP w0.381: L22.2 C200.2 79.35,111.3 arc(80.78,111.59) ANT.1
N22805505: length 24.6
  TOP w0.121: v1(71.09,88.93) 70.72,88.93 70.55,89.09 D7.1
  LYR3 w0.133: v1(71.09,88.93) 71.48,88.93 71.5,88.95 71.6,88.95 71.83,89.18 71.83,98.14 68.96,101.01 68.96,102.34 v1(64.82,106.48)
  BOTTOM w0.121: v1(64.82,106.48) 64.74,106.48 63.94,107.28 Q3.3
N22805508: length 25.1
  TOP w0.121: D8.1 70.55,87.29 v1(70.98,87.72)
  LYR3 w0.133: v1(67.44,107.09) 67.72,106.81 67.72,106.05 67.18,105.51 67.18,104.45 69.2,102.43 69.2,102.36 69.22,102.34 69.22,101.12 72.09,98.25 72.09,88.16 71.65,87.73 71.38,87.73 71.36,87.72 v1(70.98,87.72)
  BOTTOM w0.121: v1(67.44,107.09) 67.37,107.15 Q4.3
N22816281: length 5.2
  TOP w0.762: v2(82.04,82.78) 77.96,82.78 J4.3
  BOTTOM w0.635: v2(82.04,82.78) 82.8,82.78 R231.1
N22816655: length 4.5
  TOP w0.762: J5.3 78.74,97.53 80.14,96.13 v2(80.14,95.22)
  BOTTOM w0.635: R232.1 v2(80.14,95.22)
N22868112: length 2.8
  BOTTOM w0.33: R217.1 22.15,105.46 R216.2 21.82,104.71 21.59,104.48 21.59,104.11 21.32,103.85 U20.4
N22868125: length 0.8
  BOTTOM w0.33: 20.57,103.1 20.82,102.85 U20.2
N22871921: length 1.7
  TOP w0.121: R200.2 52.75,111.79 52.83,111.71 U21.12
N22871924: length 1.9
  TOP w0.121: R199.2 52.35,110.85 52.71,111.21 U21.13
N22888492: length 1.7
  TOP w0.121: 52.88,109.71 U21.16
  TOP w0.127: 52.88,109.71 52.4,109.71 R236.2
N22888495: length 1.4
  TOP w0.121: R239.2 55,106.92 U21.20
N22888517: length 2
  TOP w0.121: R238.2 52.34,107.95 53.09,108.71 U21.18
N22888520: length 1.8
  TOP w0.121: R237.2 52.93,108.92 53.22,109.21 U21.17

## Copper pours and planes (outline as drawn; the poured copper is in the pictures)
DGND on TOP: 27.28,90.22 27.71,89.79 27.71,86.64 27.38,86.31 26.47,86.31 25.96,86.82 25.73,86.82 25.41,87.13 25.41,88.46 24.92,88.95 24.92,90.37 25.12,90.58 25.65,90.58 25.76,90.68 26.19,90.68 26.64,90.22
DGND on TOP: 37.31,101.96 36.63,101.27 36.02,101.27 35.48,100.74 34.87,100.74 34.4,100.27 34.4,99.3 34.24,99.14 34.24,98.45 35.15,97.54 35.15,96.06 34.72,95.63 31.29,95.63 30.51,96.42 30.51,98.45 30.99,98.93 30.99,101.42 32.31,102.74 33.32,102.74 33.63,102.44 33.63,102.24 33.76,102.11 34.92,102.11 36.27,103.45 39.24,103.45 39.88,102.82 40.74,102.82 41.27,102.29 41.27,101.42 40.89,101.04 40.18,101.04 39.93,101.3 39.93,101.8 38.99,102.74 37.54,102.74 37.31,102.51
DGND on TOP: 3.53,105.64 16.23,105.64 17.07,104.8 17.07,103.12 15.9,101.96 11.58,101.96 10.79,101.17 10.79,95.61 11.76,94.64 15.42,94.64 16.66,93.4 16.66,87.43 16.71,87.38 17.17,87.38 17.4,87.15 17.4,86.54 16.74,85.88 16.74,84.99 15.21,83.46 11.48,83.46 10.54,82.52 10.54,79.55 8.36,77.37 4.17,77.37 3,78.54 3,105.08 3.53,105.61
DGND on TOP: 25.45,74.32 28.5,74.32 28.6,74.22 28.6,72.06 28.56,72.02 28.56,71.23 27.94,70.61 22.61,70.61 21.77,71.45 21.77,74.07 22.05,74.35 23.16,74.35 23.32,74.19 23.32,72.01 23.65,71.68 25.07,71.68 25.3,71.91 25.3,74.17
DGND on TOP: 31.5,95.48 33.6,95.48 33.91,95.17 33.91,94.79 33.5,94.39 33.5,91.59 32.87,90.96 31.78,90.96 31.52,91.21 31.52,92.43 31.37,92.58 30.56,92.58 30.38,92.76 30.38,93.14 30.48,93.24 31.19,93.24 31.34,93.4 31.34,95.33
DGND on TOP: 34.62,82.02 35.81,82.02 36.17,81.66 36.17,78.46 35.59,77.88 34.42,77.88 34.19,78.11 34.19,81.58
DGND on TOP: outline of 116 points within 56.69,71.07 86.44,117.58
